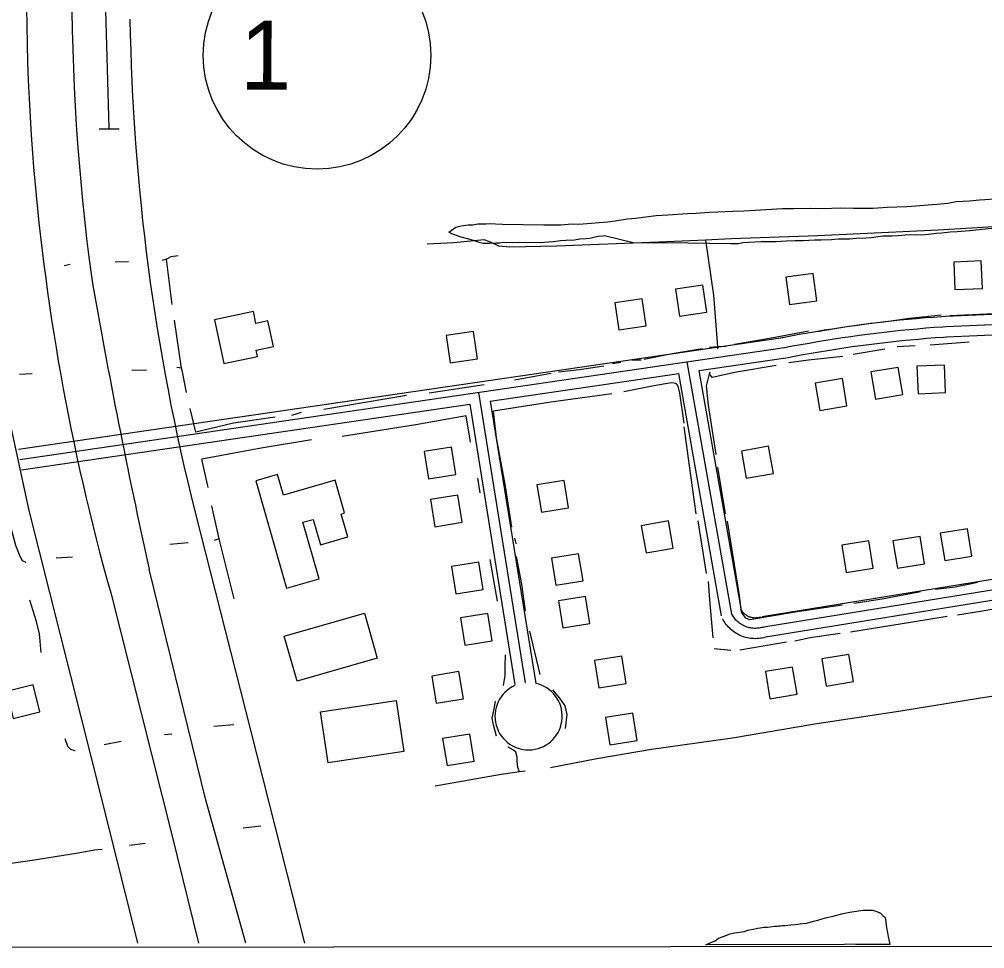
# Model space of a CAD drawing. Extents: x 3297735 to 3335592, y 670436 to 695807.
# Drawn here: x 3303596 to 3304997, y 675812 to 677160 of the extents above; entities that cross this region are included whole.
import ezdxf

# ---------------------------------------------------------------- set-up
doc = ezdxf.new("R2010")
doc.units = 0
for name, color, linetype in [('V-BLDG-OTLN', 7, 'Continuous'), ('V-GRID-FRAM', 7, 'Continuous'), ('V-ROAD-CNTR', 7, 'Continuous'), ('V-ROAD-IDEN', 7, 'Continuous'), ('V-SITE-VEGE', 7, 'Continuous'), ('V-TOPO-SHOR', 7, 'Continuous')]:
    doc.layers.add(name, color=color, linetype=linetype)

msp = doc.modelspace()

# ---------------------------------------------------------------- linework, layer by layer
at = {"layer": 'V-BLDG-OTLN'}
for points in [[(3304953.4, 676768), (3304993.4, 676769.7), (3304991.6, 676809.7), (3304951.7, 676807.9)], [(3304713.3, 676746.7), (3304753, 676751.9), (3304747.8, 676791.5), (3304708.1, 676786.3)], [(3304553.7, 676729.4), (3304593.3, 676735.2), (3304587.5, 676774.7), (3304547.9, 676768.9)], [(3304465.7, 676709.5), (3304505.3, 676715.3), (3304499.5, 676754.9), (3304459.9, 676749.1)], [(3303879.3, 676724), (3303892.8, 676660.8), (3303941.5, 676671.2), (3303939.6, 676680.1), (3303964.7, 676685.5), (3303956.7, 676722.6), (3303939.5, 676718.9), (3303935.8, 676736.1)], [(3304221.4, 676661.8), (3304261, 676667.6), (3304255.2, 676707.2), (3304215.6, 676701.4)], [(3304871.1, 676655.3), (3304831.6, 676648.7), (3304838.2, 676609.3), (3304877.7, 676615.9)], [(3304938.1, 676658.6), (3304898.2, 676656.9), (3304899.9, 676616.9), (3304939.9, 676618.6)], [(3304790.2, 676638.9), (3304750.7, 676632.3), (3304757.3, 676592.9), (3304796.8, 676599.5)], [(3304229.4, 676499.9), (3304223, 676539.4), (3304183.5, 676533.1), (3304189.9, 676493.6)], [(3304643.7, 676533.9), (3304650.6, 676494.5), (3304690, 676501.4), (3304683, 676540.8)], [(3303939.2, 676490.7), (3303983.9, 676334.9), (3304031, 676348.5), (3304007.5, 676430.5), (3304022.6, 676434.8), (3304033.2, 676397.9), (3304072.5, 676409.2), (3304062.9, 676442.5), (3304068.1, 676444), (3304054.5, 676491.6), (3303979.4, 676470), (3303970.8, 676499.8)], [(3304347.1, 676484.8), (3304353.5, 676445.3), (3304393, 676451.6), (3304386.6, 676491.1)], [(3304238.5, 676430.5), (3304232.1, 676470), (3304192.6, 676463.6), (3304199, 676424.1)], [(3304498.4, 676425.6), (3304505.4, 676386.2), (3304544.8, 676393.2), (3304537.8, 676432.6)], [(3304938.6, 676375.2), (3304978.1, 676381.6), (3304971.7, 676421.1), (3304932.2, 676414.7)], [(3304795.5, 676357.7), (3304835, 676364.1), (3304828.6, 676403.6), (3304789.1, 676397.2)], [(3304869.9, 676364), (3304909.4, 676370.4), (3304903, 676409.8), (3304863.5, 676403.4)], [(3304368, 676378.5), (3304374.4, 676339.1), (3304413.9, 676345.4), (3304407.5, 676384.9)], [(3304269.1, 676333.1), (3304262.7, 676372.6), (3304223.2, 676366.3), (3304229.6, 676326.8)], [(3304378.1, 676316.8), (3304384.4, 676277.3), (3304423.9, 676283.6), (3304417.6, 676323.1)], [(3303980.5, 676265.2), (3304096.7, 676298.8), (3304115.5, 676233.6), (3303999.3, 676200)], [(3304282.1, 676258.7), (3304275.7, 676298.2), (3304236.2, 676291.8), (3304242.6, 676252.3)], [(3304430.6, 676229.9), (3304437, 676190.4), (3304476.4, 676196.7), (3304470.1, 676236.2)], [(3304766.6, 676193), (3304806.1, 676199.4), (3304799.6, 676238.9), (3304760.2, 676232.5)], [(3304240.3, 676174.4), (3304233.9, 676213.9), (3304194.5, 676207.5), (3304200.8, 676168)], [(3304684.8, 676174.6), (3304724.3, 676181), (3304717.9, 676220.5), (3304678.4, 676214.1)], [(3303587.1, 676146.1), (3303625.9, 676155.8), (3303616.2, 676194.6), (3303577.4, 676185)], [(3304033.2, 676155.4), (3304142.6, 676172.1), (3304153.8, 676098.1), (3304044.4, 676081.4)], [(3304446.6, 676147.2), (3304452.9, 676107.7), (3304492.4, 676114.1), (3304486.1, 676153.6)], [(3304256, 676083.9), (3304249.7, 676123.4), (3304210.2, 676117), (3304216.6, 676077.6)]]:
    msp.add_lwpolyline(points, close=True, dxfattribs=at)
at = {"layer": 'V-GRID-FRAM'}
msp.add_lwpolyline([(3301851.4, 693996.5), (3333375, 694028.6), (3333401.5, 675844.1), (3301862, 675812)], close=True, dxfattribs=at)
at = {"layer": 'V-ROAD-CNTR'}
for points in [[(3303767.9, 675819.8), (3303715.7, 676029.3), (3303610.4, 676447.4), (3303575, 676611.2), (3303562.1, 676699.9), (3303548.2, 676758.4), (3303543.4, 676824.6), (3303533.3, 676905.5), (3303529.7, 676967.4), (3303526.1, 677026.9), (3303528.3, 677087.6), (3303522.9, 677144.2), (3303525.6, 677209.7), (3303523.8, 677268.8), (3303525.9, 677326.2), (3303536, 677459.4), (3303537.9, 677522.5), (3303544.1, 677577.1), (3303536.8, 677606), (3303519, 677635), (3303503.6, 677659.2), (3303484.4, 677673.8), (3303437.7, 677699.9)], [(3304940, 676729.6), (3305524.7, 676755)], [(3304940.7, 676714.6), (3305541.2, 676740.7)], [(3304703.2, 676698.7), (3304715.2, 676701), (3304727.3, 676703.3), (3304739.4, 676705.4), (3304751.5, 676707.5), (3304763.7, 676709.5), (3304775.8, 676711.4), (3304787.9, 676713.3), (3304800.1, 676715.1), (3304812.3, 676716.7), (3304824.5, 676718.4), (3304836.7, 676719.9), (3304848.9, 676721.3), (3304861.1, 676722.7), (3304873.3, 676724), (3304885.5, 676725.2), (3304897.8, 676726.3), (3304910, 676727.4), (3304922.3, 676728.3), (3304934.5, 676729.2), (3304939.7, 676729.6)], [(3304941.3, 676699.6), (3305527.6, 676725.1)], [(3304706, 676684), (3304718, 676686.3), (3304730, 676688.5), (3304742, 676690.6), (3304754, 676692.7), (3304766.1, 676694.7), (3304778.1, 676696.6), (3304790.2, 676698.5), (3304802.2, 676700.2), (3304814.3, 676701.9), (3304826.4, 676703.5), (3304838.5, 676705), (3304850.6, 676706.4), (3304862.7, 676707.8), (3304874.8, 676709.1), (3304887, 676710.3), (3304899.1, 676711.4), (3304911.3, 676712.4), (3304923.4, 676713.4), (3304935.6, 676714.3), (3304940.7, 676714.6)], [(3303594.8, 676536.4), (3304703.9, 676698.8)], [(3304708.9, 676669.2), (3304720.8, 676671.5), (3304732.7, 676673.7), (3304744.6, 676675.9), (3304756.5, 676677.9), (3304768.5, 676679.9), (3304780.4, 676681.8), (3304792.4, 676683.6), (3304804.3, 676685.4), (3304816.3, 676687), (3304828.3, 676688.6), (3304840.3, 676690.1), (3304852.3, 676691.5), (3304864.3, 676692.9), (3304876.4, 676694.1), (3304888.4, 676695.3), (3304900.4, 676696.4), (3304912.5, 676697.5), (3304924.5, 676698.4), (3304936.6, 676699.3), (3304941.7, 676699.6)], [(3303597, 676521.6), (3304706, 676684)], [(3304582.5, 676650.7), (3304708.2, 676669.1)], [(3304629.7, 676297.4), (3304565, 676663.3)], [(3304279.4, 676606.3), (3304552.8, 676646.4)], [(3304614.9, 676294.8), (3304552.8, 676646.4)], [(3304644.4, 676300), (3304582.5, 676650.7)], [(3304262.1, 676619), (3304330, 676197.6)], [(3303599.2, 676506.7), (3304249.7, 676602)], [(3304249.7, 676602), (3304315.1, 676195.2)], [(3304279.4, 676606.3), (3304345.3, 676196.8)], [(3305987.7, 676491.3), (3304676.3, 676278.6)], [(3303850.7, 676446.5), (3303932.1, 676127), (3304009.8, 675820)], [(3305556, 676436.5), (3304673.9, 676293.4)], [(3305558.9, 676406.6), (3304678.7, 676263.8)], [(3303925, 675819.9), (3303866.2, 676029.4), (3303784.6, 676362.5)], [(3303728.7, 676328.3), (3303817.5, 675977.2), (3303856, 675819.9)], [(3304676.3, 676278.6), (3304674.6, 676278.1), (3304672.9, 676277.7), (3304671.2, 676277.3), (3304669.4, 676277), (3304667.7, 676276.8), (3304665.9, 676276.7), (3304664.2, 676276.6), (3304662.4, 676276.6), (3304660.6, 676276.8), (3304658.9, 676277), (3304657.2, 676277.2), (3304655.4, 676277.6), (3304653.7, 676278), (3304652, 676278.5), (3304650.4, 676279.1), (3304648.7, 676279.7), (3304647.1, 676280.5), (3304645.6, 676281.3), (3304644, 676282.1), (3304642.6, 676283.1), (3304641.1, 676284.1), (3304639.7, 676285.1), (3304638.4, 676286.3), (3304637.1, 676287.5), (3304635.8, 676288.7), (3304634.7, 676290), (3304633.5, 676291.4), (3304632.5, 676292.8), (3304631.5, 676294.2), (3304630.6, 676295.7), (3304629.7, 676297.3), (3304629.7, 676297.4)], [(3304671.8, 676293), (3304670.5, 676292.5), (3304669.4, 676292.3), (3304668.4, 676292), (3304667.3, 676291.9), (3304666.2, 676291.7), (3304665.2, 676291.7), (3304664.1, 676291.6), (3304663, 676291.6), (3304661.9, 676291.7), (3304660.9, 676291.8), (3304659.8, 676292), (3304658.7, 676292.2), (3304657.7, 676292.5), (3304656.7, 676292.8), (3304655.6, 676293.1), (3304654.6, 676293.5), (3304653.7, 676294), (3304652.7, 676294.5), (3304651.8, 676295), (3304650.8, 676295.6), (3304650, 676296.2), (3304649.1, 676296.8), (3304648.3, 676297.5), (3304647.5, 676298.3), (3304646.7, 676299), (3304646, 676299.8), (3304645.3, 676300.7), (3304644.7, 676301.5), (3304644.1, 676302.4), (3304643.5, 676303.3), (3304642.9, 676304.4), (3304643, 676304.3)], [(3304680.7, 676264.3), (3304678.7, 676263.7), (3304676.3, 676263.1), (3304674, 676262.6), (3304671.5, 676262.2), (3304669.1, 676261.9), (3304666.7, 676261.7), (3304664.2, 676261.6), (3304661.8, 676261.7), (3304659.4, 676261.8), (3304656.9, 676262.1), (3304654.5, 676262.4), (3304652.1, 676262.9), (3304649.8, 676263.5), (3304647.4, 676264.2), (3304645.1, 676265), (3304642.8, 676265.9), (3304640.6, 676266.9), (3304638.4, 676268.1), (3304636.3, 676269.3), (3304634.3, 676270.6), (3304632.3, 676272), (3304630.3, 676273.5), (3304628.5, 676275), (3304626.7, 676276.7), (3304624.9, 676278.4), (3304623.3, 676280.2), (3304621.7, 676282.1), (3304620.3, 676284.1), (3304618.9, 676286.1), (3304617.6, 676288.2), (3304616.5, 676290.2), (3304616.4, 676290.5)]]:
    msp.add_lwpolyline(points, dxfattribs=at)
for centre, radius, start, end in [((3306750.9, 677199.5), 3144.3, 168.869, 184.2595), ((3306853.4, 677212.8), 3181.2, 171.8078, 187.6817), ((3306894.7, 677210.7), 3138.4, 180.9216, 194.0917), ((3306890.7, 677219.5), 3285.2, 184.4273, 195.7406), ((3312800.7, 678361.9), 9235.2, 189.8152, 192.50333), ((3304334.9, 676149.1), 48.8, 114.2026, 77.7485)]:
    msp.add_arc(centre, radius, start, end, dxfattribs=at)
at = {"layer": 'V-ROAD-IDEN'}
msp.add_circle((3304028.1, 677107.8), 165, dxfattribs=at)
at = {"layer": 'V-SITE-VEGE'}
for p, q in [((3304761, 675855.1), (3304767.7, 675857.2)), ((3304767.7, 675857.2), (3304776.6, 675859.3)), ((3304776.6, 675859.3), (3304782.2, 675860.8)), ((3304782.2, 675860.8), (3304789.4, 675862.4)), ((3304789.4, 675862.4), (3304795.6, 675863.9)), ((3304795.6, 675863.9), (3304803.9, 675865.4)), ((3304803.9, 675865.4), (3304820.1, 675867.9)), ((3304820.1, 675867.9), (3304833.9, 675867.7)), ((3304833.9, 675867.7), (3304840, 675865.9)), ((3304840, 675865.9), (3304845.5, 675863.6)), ((3304845.5, 675863.6), (3304848.8, 675860.2)), ((3304848.8, 675860.2), (3304852, 675857.4)), ((3304852, 675857.4), (3304852.6, 675855.1)), ((3304670.9, 675842.3), (3304676.5, 675843.3)), ((3304676.5, 675843.3), (3304681.5, 675843.2)), ((3304681.5, 675843.2), (3304685.4, 675843.7)), ((3304685.4, 675843.7), (3304691.5, 675844.7)), ((3304691.5, 675844.7), (3304695.4, 675844.6)), ((3304695.4, 675844.6), (3304697.6, 675845.1)), ((3304697.6, 675845.1), (3304700.4, 675845.1)), ((3304700.4, 675845.1), (3304702.6, 675845.6)), ((3304702.6, 675845.6), (3304707, 675845.5)), ((3304707, 675845.5), (3304715.4, 675846.5)), ((3304715.4, 675846.5), (3304721.5, 675846.9)), ((3304721.5, 675846.9), (3304732.6, 675848.4)), ((3304732.6, 675848.4), (3304738.7, 675848.8)), ((3304738.7, 675848.8), (3304748.2, 675852)), ((3304748.2, 675852), (3304754.3, 675853.5)), ((3304754.3, 675853.5), (3304761, 675855.1)), ((3304852.6, 675855.1), (3304853, 675850.1)), ((3304853, 675850.1), (3304854, 675842.9)), ((3304854, 675842.9), (3304857.1, 675827.3)), ((3304610.2, 675827.2), (3304622.5, 675831.5)), ((3304622.5, 675831.5), (3304625.3, 675833.1)), ((3304625.3, 675833.1), (3304633.6, 675835.1)), ((3304633.6, 675835.1), (3304647.5, 675837.1)), ((3304647.5, 675837.1), (3304653.1, 675838.7)), ((3304653.1, 675838.7), (3304663.1, 675840.7)), ((3304663.1, 675840.7), (3304667, 675841.8)), ((3304667, 675841.8), (3304670.9, 675842.3)), ((3304592.1, 675817.7), (3304592.8, 675818.1)), ((3304793.3, 675817.9), (3304592.1, 675817.7)), ((3304592.8, 675818.1), (3304599.5, 675820.8)), ((3304599.5, 675820.8), (3304605.7, 675823.4)), ((3304605.7, 675823.4), (3304610.2, 675827.2)), ((3304795.3, 675818.4), (3304793.3, 675817.9)), ((3304809.7, 675818.2), (3304795.3, 675818.4)), ((3304811.4, 675817.9), (3304809.7, 675818.2)), ((3304859.1, 675818), (3304811.4, 675817.9)), ((3304857.1, 675827.3), (3304859.1, 675818))]:
    msp.add_line(p, q, dxfattribs=at)
for points in [[(3304297.3, 676862.9), (3304357.2, 676861.9), (3304372.1, 676862.2), (3304381.6, 676862), (3304397.7, 676863.4), (3304407.7, 676863.2), (3304449.3, 676866.4), (3304460.4, 676867.8), (3304478.2, 676870.8), (3304489.9, 676871.7), (3304519.9, 676875.7), (3304537.1, 676876.5), (3304565.5, 676878.7), (3304578.2, 676879.1), (3304597.1, 676880.4), (3304609.3, 676880.7), (3304631, 676882), (3304647.1, 676882.3), (3304663.8, 676883.1), (3304679.3, 676884.5), (3304703.2, 676885.7), (3304719.3, 676885.5), (3304743.7, 676886.1), (3304762, 676885.8), (3304787.5, 676886.5), (3304806.4, 676886.1), (3304834.7, 676886.2), (3304855.2, 676887.5), (3304883.5, 676888.7), (3304926.9, 676891.8), (3304943, 676893.7), (3304955.2, 676895.7), (3304974.7, 676897), (3304989.1, 676898.4), (3305011.9, 676899.7)], [(3305006.7, 676856.5), (3304974.4, 676853.2), (3304956.7, 676851.9), (3304946.7, 676851.5), (3304934.4, 676850), (3304926.7, 676849.6), (3304915, 676848.2), (3304905.5, 676847.2), (3304896.1, 676847.4), (3304881.1, 676847.1), (3304871.1, 676846.2), (3304861.7, 676845.8), (3304848.9, 676845.4), (3304831.7, 676843), (3304823.9, 676842.6), (3304810.6, 676842.2), (3304801.1, 676841.3), (3304784.5, 676841), (3304774.5, 676840.1), (3304759.5, 676839.8), (3304749.5, 676840), (3304733.4, 676838.6), (3304721.8, 676838.8), (3304709, 676838.5), (3304693.5, 676837.6), (3304672.4, 676837.5), (3304645.7, 676835.7), (3304639.6, 676834.7), (3304628.5, 676834.3), (3304534.8, 676836), (3304517.6, 676835.2), (3304486.5, 676835.7), (3304445.1, 676845.9), (3304442.8, 676845.4), (3304436.2, 676845), (3304431.7, 676843.9), (3304423.9, 676842.4), (3304418.4, 676841.9), (3304409.5, 676841), (3304401.7, 676840), (3304388.9, 676839.1), (3304381.2, 676838.7), (3304371.1, 676837.2), (3304363.9, 676836.8), (3304351.7, 676835.9), (3304321.8, 676836.4), (3304311.2, 676836.1), (3304297.9, 676836.3), (3304292.9, 676835.3), (3304287.3, 676835.4), (3304278.5, 676835), (3304269, 676835.1), (3304264.6, 676835.8), (3304255.2, 676839.3), (3304248.1, 676841.1), (3304237, 676844), (3304228.7, 676846.9), (3304223.8, 676849.2), (3304219.4, 676851.5), (3304229.5, 676858.6), (3304237.3, 676860.7), (3304247.3, 676862.2), (3304254, 676862), (3304261.2, 676863.6), (3304272.9, 676863.4), (3304279.5, 676863.8), (3304286.7, 676863.7), (3304297.3, 676862.9)]]:
    msp.add_lwpolyline(points, dxfattribs=at)
at = {"layer": 'V-TOPO-SHOR'}
for p, q in [((3303726.3, 677002.2), (3303721.5, 677173.5)), ((3303741.1, 677000.8), (3303712, 677000.9)), ((3303670.1, 676804.3), (3303661.2, 676802.6)), ((3303754.7, 676808.5), (3303735.3, 676807.7)), ((3303831.3, 676654), (3303821.5, 676723.7)), ((3304895.6, 676686.7), (3304869.6, 676685.1)), ((3304974.2, 676691.9), (3304917.4, 676687.6)), ((3304851.8, 676681.6), (3304805.7, 676673.7)), ((3304468.9, 676662.2), (3304456.5, 676660.5)), ((3304498.2, 676665.7), (3304484.9, 676665.7)), ((3303615, 676645.7), (3303596.4, 676644.9)), ((3303780.8, 676651.4), (3303759.6, 676650.6)), ((3304367.8, 676646.6), (3304314.6, 676636.9)), ((3304270.3, 676630), (3304190.5, 676617.8)), ((3304157.7, 676614.3), (3304038, 676594.3)), ((3303852, 676561.3), (3303844.1, 676595.7)), ((3304005.2, 676589.9), (3303991, 676585.5)), ((3303870.3, 676481), (3303861, 676522.3)), ((3304620.8, 676442.9), (3304609.4, 676510.3)), ((3304264.6, 676473.1), (3304261.1, 676494.4)), ((3303886.3, 676406.5), (3303875.5, 676454.5)), ((3304593, 676356.1), (3304580.8, 676432.4)), ((3304316.7, 676399.4), (3304314.9, 676407.4)), ((3303840.9, 676400.8), (3303814.5, 676398.2)), ((3303673.3, 676380.1), (3303649.5, 676378.4)), ((3304289.8, 676316.2), (3304279.4, 676376.5)), ((3304351.6, 676209.7), (3304336.7, 676272.6)), ((3304708.9, 676256.6), (3304641.5, 676245.2)), ((3304628.2, 676244.4), (3304604.3, 676247.1)), ((3303907.3, 676136.9), (3303878.2, 676134.4)), ((3303817.3, 676123.1), (3303806.7, 676122.2)), ((3303744, 676112.7), (3303719.3, 676107.5)), ((3303946.6, 675989.6), (3303921, 675987)), ((3303778.9, 675964.4), (3303756, 675961.8))]:
    msp.add_line(p, q, dxfattribs=at)
for points in [[(3305549.7, 676789.4), (3305545.1, 676881.8), (3305475.1, 676881.2), (3305289, 676871.9), (3305171.1, 676866.9), (3305041.7, 676861.1), (3304929.1, 676854.3), (3304754.5, 676845.9), (3304628.7, 676841.8), (3304591.7, 676840), (3304524.1, 676836.7), (3304375.2, 676830.9), (3304307.8, 676829.4), (3304291.9, 676831.2), (3304278.6, 676837.4), (3304270.6, 676840.1), (3304226.3, 676835.8), (3304187.6, 676834)], [(3304591.7, 676840), (3304603, 676760.2), (3304608.9, 676684.9), (3304609.1, 676682)], [(3303818.1, 676746.6), (3303809.7, 676812.1), (3303803.2, 676810.1)], [(3303826.8, 676817.3), (3303816.2, 676815.5), (3303809.7, 676812.1)], [(3304933.5, 676731), (3304887.7, 676726.2), (3304846.7, 676720.4)], [(3305091.2, 676735), (3305010.4, 676732.9), (3304945.9, 676730.1)], [(3304834.3, 676719.5), (3304790.5, 676713.2), (3304753.5, 676706.7)], [(3304741.1, 676707.6), (3304687.1, 676697.6), (3304633.8, 676688.4)], [(3304621.4, 676685.7), (3304608.9, 676684.9), (3304597.5, 676684)], [(3304586.8, 676682.3), (3304543.1, 676675), (3304502.6, 676666.6)], [(3304790.6, 676671.1), (3304740.9, 676665.6), (3304712.6, 676661.6)], [(3304444.1, 676657), (3304408.9, 676651.5), (3304378.5, 676648.3)], [(3304694, 676658.1), (3304636.7, 676648.3), (3304601.3, 676640.4), (3304597.6, 676646)], [(3303838.9, 676618.7), (3303833.1, 676648.7), (3303831.3, 676654), (3303824.9, 676654.9)], [(3304606.8, 676528.9), (3304595.8, 676600.3), (3304593.2, 676628.6), (3304597.6, 676646), (3304598.3, 676648.6)], [(3304560.8, 676574.2), (3304554.5, 676617.6), (3304551.9, 676628.2), (3304549.2, 676631.7), (3304542.1, 676632.6), (3304516.5, 676628.3), (3304473.2, 676619.7)], [(3304455.5, 676617.1), (3304367.2, 676604.8), (3304284.2, 676591.8)], [(3304310.5, 676423.4), (3304301.6, 676483.1), (3304288.5, 676552.9), (3304284.2, 676591.8)], [(3303967.1, 676582.9), (3303907.1, 676574.3), (3303852, 676561.3)], [(3304250.6, 676546.7), (3304244.6, 676584.8), (3304171.3, 676571.7), (3304064.5, 676555.2)], [(3304578.2, 676443), (3304570.9, 676494.8), (3304560.8, 676568.9)], [(3304020.2, 676550), (3303946.9, 676537.9), (3303861, 676522.3)], [(3303606.3, 676372.3), (3303600.9, 676374.8), (3303597.4, 676381), (3303591.3, 676396.9), (3303579.9, 676438.5), (3303574.8, 676468.6)], [(3304789.8, 676310.2), (3304721.4, 676300.1), (3304656, 676288.8), (3304649.9, 676291.5), (3304643.7, 676300.3), (3304641.1, 676324.2), (3304623.4, 676432.3)], [(3303907.8, 676319.5), (3303886.3, 676406.5), (3303878.9, 676404.2)], [(3304330.6, 676301.9), (3304325, 676340.9), (3304317.5, 676380.8)], [(3304602.5, 676263.1), (3304597.8, 676318.1), (3304595.7, 676344.6)], [(3304986.6, 676343.3), (3304953.7, 676336.6), (3304925.4, 676332.9)], [(3304903.3, 676329.4), (3304847.7, 676319.2), (3304806.6, 676312.8)], [(3303628, 676241.8), (3303625.4, 676268.7), (3303621, 676286.4), (3303611.4, 676317.7)], [(3305037, 676309.5), (3304990.7, 676301.1), (3304957.2, 676295.6)], [(3304942.2, 676293.8), (3304891.8, 676285.5), (3304802.1, 676271.2)], [(3304787, 676269.4), (3304743.4, 676262.9), (3304721.3, 676258.3)], [(3304298.4, 676193.9), (3304301, 676208.4), (3304301, 676221.7), (3304301.2, 676238.2)], [(3305154.6, 676201.1), (3305078.7, 676188.7), (3304987.7, 676174.9), (3304874.7, 676156.6), (3304750.1, 676137.5), (3304630.8, 676117.5), (3304513.3, 676101.1), (3304433.8, 676087.2), (3304366.7, 676074.1)], [(3304388.6, 676131.6), (3304390.7, 676151.7), (3304388.1, 676164.1), (3304380.2, 676175.6), (3304370.1, 676187.5)], [(3304288.4, 676120.3), (3304284, 676136.9), (3304282.3, 676146.6), (3304284.9, 676159.9), (3304286.8, 676170.9)], [(3303677, 676098.8), (3303670.9, 676100.7), (3303666.5, 676105.1), (3303662.9, 676116.4)], [(3304321.9, 676068.5), (3304319.2, 676075), (3304318.3, 676083.9), (3304318.3, 676090), (3304316.6, 676097.1), (3304313, 676099.8), (3304305.2, 676104.3)], [(3304329.9, 676069.7), (3304321.9, 676068.5), (3304295.1, 676064.6), (3304199.6, 676047.9)], [(3303716.3, 675955.8), (3303705.3, 675954.7), (3303681.4, 675950.4), (3303615, 675939.9), (3303506.9, 675924.3), (3303360, 675899), (3303323.7, 675893.8), (3303232.5, 675881.6), (3303166.9, 675871.2), (3303068.7, 675855.5), (3302985.4, 675841.6), (3302884.5, 675824.2), (3302834, 675815.9)]]:
    msp.add_lwpolyline(points, dxfattribs=at)

# ---------------------------------------------------------------- texts
at = {"layer": 'V-ROAD-IDEN'}
msp.add_text(' 1 ', height=100, rotation=359.688, dxfattribs=at).set_placement((3303879, 677058.6))

doc.saveas('drawing.dxf')
